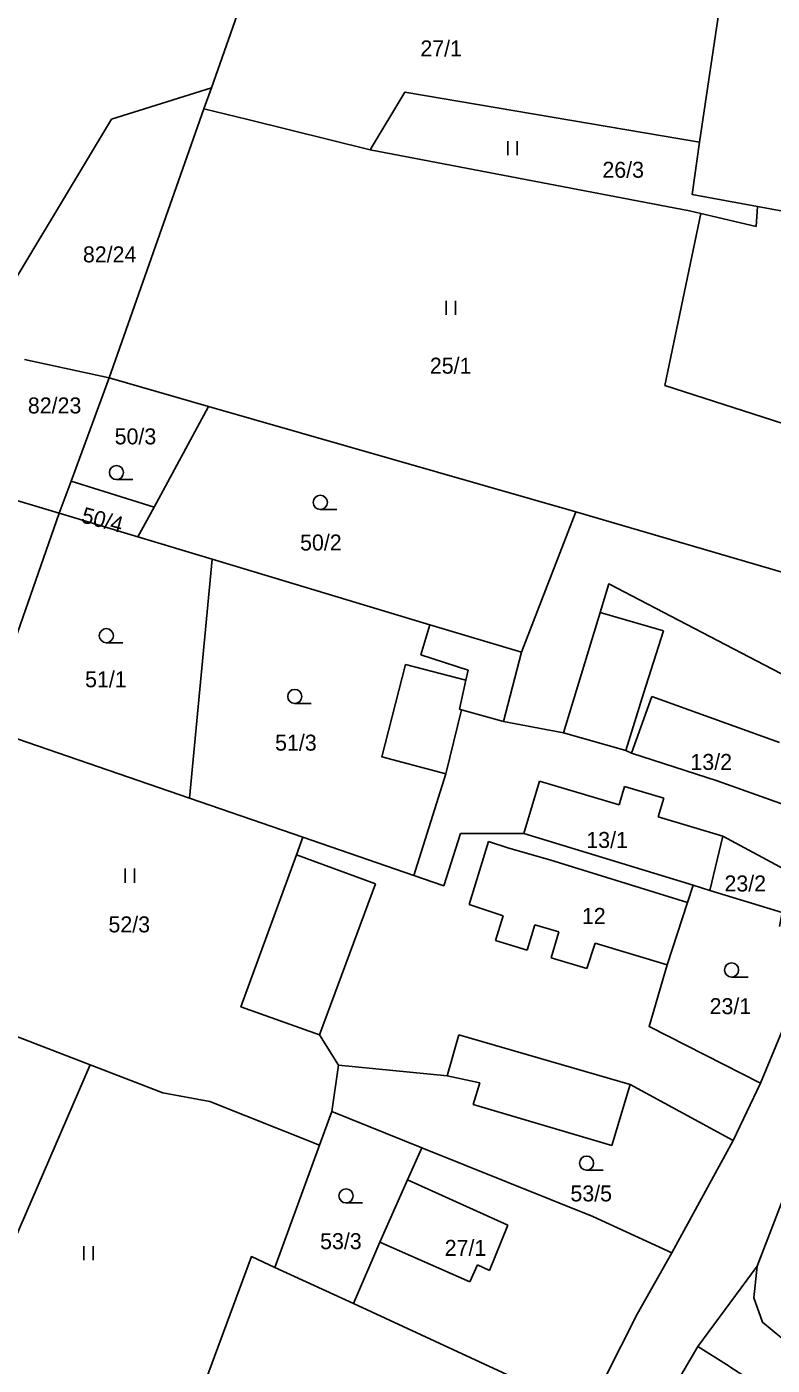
# Model space of a CAD drawing. Extents: x -746176 to -739709, y -1128407 to -1124482.
# Drawn here: x -743036.1 to -742956.8, y -1127574.6 to -1127432.2 of the extents above; entities that cross this region are included whole.
import ezdxf

# ---------------------------------------------------------------- set-up
doc = ezdxf.new("R2010")
doc.units = 0
for name, color, linetype in [('Vrstva 33', 7, 'Continuous'), ('Vrstva 42', 7, 'Continuous'), ('Vrstva 44', 7, 'Continuous'), ('Vrstva 47', 7, 'Continuous')]:
    doc.layers.add(name, color=color, linetype=linetype)

msp = doc.modelspace()

# ---------------------------------------------------------------- linework, layer by layer
at = {"layer": 'Vrstva 33'}
for p, q in [((-743016.5, -1127438.72), (-743010.06, -1127420.45)), ((-742962.06, -1127427.67), (-742964.54, -1127444.49)), ((-743017.29, -1127440.95), (-743016.5, -1127438.72)), ((-743017.29, -1127440.95), (-743027.39, -1127469.59)), ((-742968.23, -1127470.39), (-742964.4, -1127452.09)), ((-743027.39, -1127469.59), (-743036.38, -1127467.62)), ((-743027.39, -1127469.59), (-743031.43, -1127480.55)), ((-743027.39, -1127469.59), (-743016.81, -1127472.62)), ((-742947.25, -1127477.16), (-742968.23, -1127470.39)), ((-743016.81, -1127472.62), (-743022.6, -1127483.32)), ((-743016.81, -1127472.62), (-742977.71, -1127483.81)), ((-743031.43, -1127480.55), (-743032.69, -1127483.96)), ((-743031.43, -1127480.55), (-743022.6, -1127483.32)), ((-743032.69, -1127483.96), (-743040.81, -1127481.55)), ((-743032.69, -1127483.96), (-743040.66, -1127506.77)), ((-743024.31, -1127486.49), (-743032.69, -1127483.96)), ((-743022.6, -1127483.32), (-743024.31, -1127486.49)), ((-742977.71, -1127483.81), (-742983.49, -1127498.74)), ((-742954.21, -1127490.71), (-742977.71, -1127483.81)), ((-743024.31, -1127486.49), (-743016.42, -1127488.87)), ((-743018.83, -1127514.29), (-743016.42, -1127488.87)), ((-742983.49, -1127498.74), (-742985.43, -1127506.13)), ((-743040.66, -1127506.77), (-743018.83, -1127514.29)), ((-742979.03, -1127507.34), (-742985.43, -1127506.13)), ((-743018.83, -1127514.29), (-743006.77, -1127518.44)), ((-742983.25, -1127518.03), (-742989.99, -1127518.04)), ((-742965.23, -1127523.55), (-742983.25, -1127518.03)), ((-742994.94, -1127522.52), (-743006.77, -1127518.44)), ((-742965.23, -1127523.55), (-742963.44, -1127524.1)), ((-742958.07, -1127544.59), (-742952.01, -1127529.96)), ((-743029.41, -1127542.64), (-743050.32, -1127534.62)), ((-743029.41, -1127542.64), (-743044.5, -1127577.53)), ((-743003.69, -1127547.61), (-743002.99, -1127542.69)), ((-742960.97, -1127550.69), (-742958.07, -1127544.59)), ((-743005.01, -1127551.2), (-743003.69, -1127547.61)), ((-742994.1, -1127551.47), (-743003.69, -1127547.61)), ((-742960.97, -1127550.69), (-742967.51, -1127562.65)), ((-743009.74, -1127564.2), (-743005.01, -1127551.2)), ((-743001.38, -1127568.05), (-743009.74, -1127564.2)), ((-742964.75, -1127572.6), (-742958.43, -1127564.08)), ((-742979.47, -1127578.16), (-743001.38, -1127568.05))]:
    msp.add_line(p, q, dxfattribs=at)
for points in [[(-743041.59, -1127466.09), (-743027.12, -1127442.06), (-743016.5, -1127438.72)], [(-742964.54, -1127444.49), (-742995.91, -1127439.17), (-742999.6, -1127445.32)], [(-742999.6, -1127445.32), (-743012.61, -1127442.11), (-743017.29, -1127440.95)], [(-742964.4, -1127452.09), (-742965.61, -1127451.81), (-742999.6, -1127445.32)], [(-742964.54, -1127444.49), (-742965.34, -1127450.06), (-742958.39, -1127451.34)], [(-742958.39, -1127451.34), (-742958.54, -1127453.46), (-742964.4, -1127452.09)], [(-742958.39, -1127451.34), (-742942.2, -1127454.33), (-742938.29, -1127453.29), (-742933.5, -1127454.97), (-742931.72, -1127454.21), (-742928.29, -1127455.5)], [(-743016.42, -1127488.87), (-742993.26, -1127495.85), (-742983.49, -1127498.74)], [(-742979.03, -1127507.34), (-742975.14, -1127494.55), (-742974.21, -1127491.49), (-742943.52, -1127507.49)], [(-742985.43, -1127506.13), (-742989.89, -1127504.88), (-742990.08, -1127504.83), (-742989.41, -1127501.75), (-742995.84, -1127500.07), (-742998.35, -1127509.89), (-742991.56, -1127511.71), (-742994.94, -1127522.52)], [(-742947.48, -1127518.45), (-742949.22, -1127517.23), (-742962.69, -1127512.44), (-742971.81, -1127509.49), (-742972.41, -1127509.22), (-742979.03, -1127507.34)], [(-742989.99, -1127518.04), (-742991.77, -1127523.61), (-742994.94, -1127522.52)], [(-742963.44, -1127524.1), (-742962.06, -1127518.33), (-742949.93, -1127524.86)], [(-743006.77, -1127518.44), (-743007.45, -1127520.31), (-743013.35, -1127536.47), (-743005, -1127539.46), (-743002.99, -1127542.69)], [(-742958.07, -1127544.59), (-742969.92, -1127538.58), (-742968.01, -1127532.03), (-742965.83, -1127525.39), (-742965.23, -1127523.55)], [(-742956.04, -1127527.94), (-742955.76, -1127526.44), (-742963.44, -1127524.1)], [(-743005.01, -1127551.2), (-743016.66, -1127546.56), (-743021.68, -1127545.63), (-743029.41, -1127542.64)], [(-743002.99, -1127542.69), (-742991.4, -1127543.81), (-742987.95, -1127544.57), (-742988.63, -1127546.87), (-742973.89, -1127551.23), (-742971.94, -1127544.76), (-742960.97, -1127550.69)], [(-742958.43, -1127564.08), (-742954.72, -1127554.49), (-742950.97, -1127547.61)], [(-742994.1, -1127551.47), (-742995.64, -1127554.9), (-742998.58, -1127561.51), (-743001.38, -1127568.05)], [(-742967.51, -1127562.65), (-742975.9, -1127558.78), (-742994.1, -1127551.47)], [(-743009.74, -1127564.2), (-743012.24, -1127563.05), (-743019.38, -1127582.4), (-743017.56, -1127583.41), (-742993.08, -1127596.96), (-742990.26, -1127591.96)], [(-742967.51, -1127562.65), (-742971.19, -1127569.17), (-742976.43, -1127579.56), (-742979.47, -1127578.16)], [(-742927.53, -1127585.44), (-742934.7, -1127582.76), (-742939.64, -1127581.23), (-742943.72, -1127578.66), (-742953.72, -1127573.43), (-742957.84, -1127570.04), (-742958.76, -1127567.42), (-742958.43, -1127564.08)], [(-742964.75, -1127572.6), (-742970.21, -1127581.92), (-742973.05, -1127587.2), (-742974.2, -1127589.77)], [(-742951.01, -1127581.4), (-742957.06, -1127577.5), (-742961.32, -1127574.78), (-742961.39, -1127574.71), (-742964.75, -1127572.6)]]:
    msp.add_lwpolyline(points, dxfattribs=at)
at = {"layer": 'Vrstva 44'}
for p, q in [((-742984.96, -1127445.9), (-742984.96, -1127444.4)), ((-742983.96, -1127445.9), (-742983.96, -1127444.4)), ((-742991.52, -1127462.88), (-742991.52, -1127461.38)), ((-742990.52, -1127462.88), (-742990.52, -1127461.38)), ((-743026.6, -1127480.4), (-743024.85, -1127480.4)), ((-743004.91, -1127483.57), (-743003.16, -1127483.57)), ((-743027.68, -1127497.75), (-743025.93, -1127497.75)), ((-743007.63, -1127504.22), (-743005.88, -1127504.22)), ((-743025.68, -1127523.28), (-743025.68, -1127521.78)), ((-743024.68, -1127523.28), (-743024.68, -1127521.78)), ((-742961.14, -1127533.31), (-742959.39, -1127533.31)), ((-742976.57, -1127553.86), (-742974.82, -1127553.86)), ((-743002.17, -1127557.34), (-743000.42, -1127557.34)), ((-743030.07, -1127563.43), (-743030.07, -1127561.93)), ((-743029.07, -1127563.43), (-743029.07, -1127561.93))]:
    msp.add_line(p, q, dxfattribs=at)
for centre in [(-743026.6, -1127479.65), (-743004.91, -1127482.82), (-743027.68, -1127497), (-743007.63, -1127503.47), (-742961.14, -1127532.56), (-742976.57, -1127553.11), (-743002.17, -1127556.59)]:
    msp.add_circle(centre, 0.75, dxfattribs=at)
at = {"layer": 'Vrstva 47'}
for p, q in [((-742975.14, -1127494.55), (-742968.39, -1127496.47)), ((-742994.2, -1127499.03), (-742993.26, -1127495.85)), ((-742970.5, -1127503.16), (-742968.39, -1127496.47)), ((-742994.2, -1127499.03), (-742989.17, -1127500.66)), ((-742989.41, -1127501.75), (-742989.17, -1127500.66)), ((-742972.41, -1127509.22), (-742970.5, -1127503.16)), ((-742971.81, -1127509.49), (-742969.62, -1127503.47)), ((-742969.62, -1127503.47), (-742956.03, -1127508.38)), ((-742991.56, -1127511.71), (-742989.89, -1127504.88)), ((-742983.25, -1127518.03), (-742981.6, -1127512.47)), ((-742981.6, -1127512.47), (-742973.1, -1127514.99)), ((-742973.1, -1127514.99), (-742972.53, -1127513.06)), ((-742972.53, -1127513.06), (-742968.35, -1127514.3)), ((-742968.94, -1127516.27), (-742968.35, -1127514.3)), ((-742968.94, -1127516.27), (-742962.06, -1127518.33)), ((-742989.07, -1127525.61), (-742987.02, -1127518.91)), ((-742987.02, -1127518.91), (-742984.85, -1127519.61)), ((-742984.85, -1127519.61), (-742980.49, -1127520.84)), ((-743007.45, -1127520.31), (-742999.03, -1127523.38)), ((-742980.49, -1127520.84), (-742965.83, -1127525.39)), ((-743005, -1127539.46), (-742999.03, -1127523.38)), ((-742989.07, -1127525.61), (-742985.46, -1127526.79)), ((-742986.28, -1127529.44), (-742985.46, -1127526.79)), ((-742982.9, -1127530.47), (-742982.08, -1127527.77)), ((-742982.08, -1127527.77), (-742979.51, -1127528.51)), ((-742986.28, -1127529.44), (-742982.9, -1127530.47)), ((-742980.35, -1127531.26), (-742979.51, -1127528.51)), ((-742976.56, -1127532.4), (-742975.66, -1127529.7)), ((-742975.66, -1127529.7), (-742968.01, -1127532.03)), ((-742980.35, -1127531.26), (-742976.56, -1127532.4)), ((-742991.4, -1127543.81), (-742990.15, -1127539.46)), ((-742990.15, -1127539.46), (-742971.94, -1127544.76)), ((-742995.64, -1127554.9), (-742984.94, -1127559.69)), ((-742986.89, -1127564.52), (-742984.94, -1127559.69)), ((-742998.58, -1127561.51), (-742988.98, -1127565.74)), ((-742988.98, -1127565.74), (-742988.19, -1127563.94)), ((-742988.19, -1127563.94), (-742986.89, -1127564.52))]:
    msp.add_line(p, q, dxfattribs=at)

# ---------------------------------------------------------------- texts
at = {"layer": 'Vrstva 42'}
for s, p in [('27/1', (-742994.26, -1127435.38)), ('26/3', (-742974.89, -1127448.29)), ('82/24', (-743030.17, -1127457.29)), ('25/1', (-742993.25, -1127469.13)), ('82/23', (-743036.03, -1127473.36)), ('50/3', (-743026.79, -1127476.65)), ('50/2', (-743007.06, -1127487.94)), ('51/1', (-743029.94, -1127502.49)), ('51/3', (-743009.72, -1127509.23)), ('13/2', (-742965.52, -1127511.28)), ('13/1', (-742976.6, -1127519.58)), ('23/2', (-742961.9, -1127524.21)), ('52/3', (-743027.45, -1127528.56)), ('12', (-742977.07, -1127527.66)), ('23/1', (-742963.48, -1127537.26)), ('53/5', (-742978.29, -1127557.18)), ('53/3', (-743004.93, -1127562.26)), ('27/1', (-742991.67, -1127562.97))]:
    msp.add_text(s, height=1.7, dxfattribs=at).set_placement(p)
msp.add_text('50/4', height=1.7, rotation=345, dxfattribs=at).set_placement((-743030.44, -1127484.93))

doc.saveas('drawing.dxf')
